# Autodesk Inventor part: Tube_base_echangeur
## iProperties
Shininess: 64.0
Length Units: 11269
Angle Units: 11279
Time Units: 11290
Mass Units: 11283
Length Display Precision: 3
Angle Display Precision: 2
Compacted: True
Part Number: Tube_base_echangeur
Document SubType Name: Modeling
Created: 2008-02
Material: Acier inoxydable, austénitique
Designer: Pascal
Density: 0.0
Volumn: 0.0
Area: 0.0
PropertySet Name: Model Information
Control State: 0
Master: False
Checked Out: False
MATIERE_PIECE: X2CrNi 18-11
OBSERVATIONS: Øext 610 ep 6
DESIGNATION: Tube base corps
Author: Pascal
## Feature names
1. Extrusion1
2. Extrusion2
3. Extrusion3
